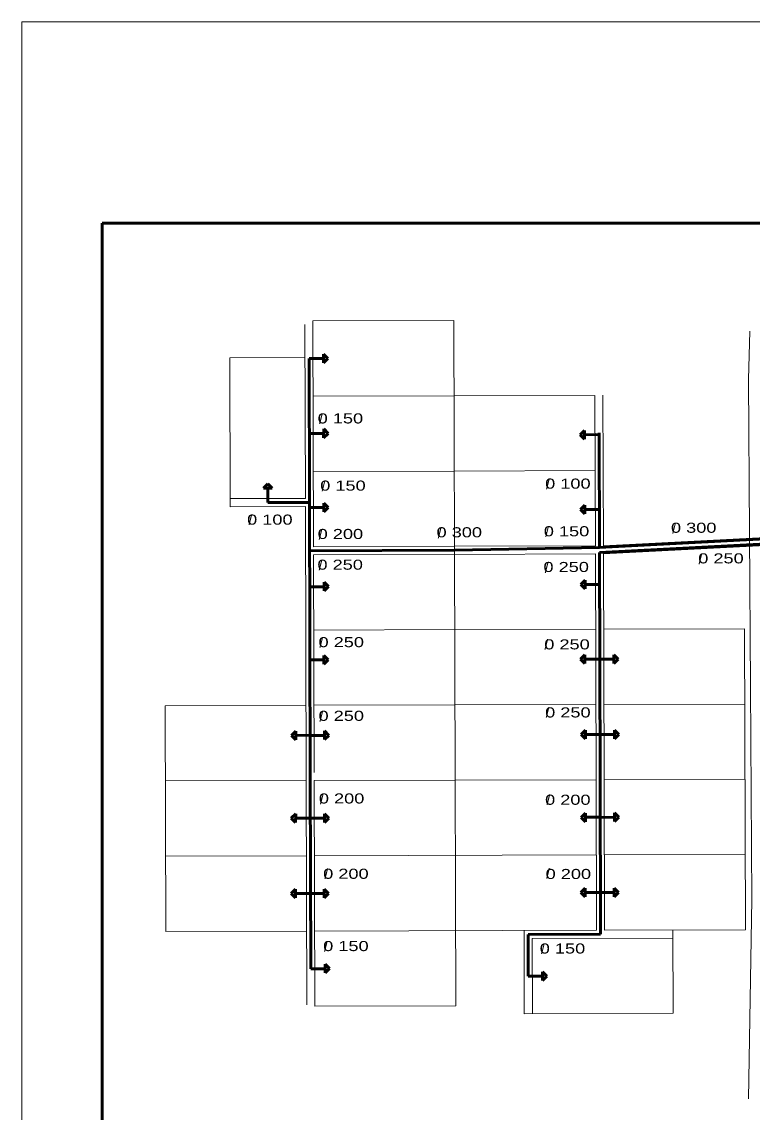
# Model space of a CAD drawing. Extents: x 312964 to 351929, y 9004151 to 9034973.
# Drawn here: x 334316 to 336131, y 9019423 to 9022132 of the extents above; entities that cross this region are included whole.
import ezdxf
from ezdxf.enums import TextEntityAlignment as Align

# ---------------------------------------------------------------- set-up
doc = ezdxf.new("R2010")
doc.units = 0
doc.header["$LTSCALE"] = 10
for name, color, linetype, lineweight in [('1', 7, 'Continuous', 13), ('2', 7, 'Continuous', 53), ('6', 7, 'Continuous', 13)]:
    doc.layers.add(name, color=color, linetype=linetype, lineweight=lineweight)

msp = doc.modelspace()

# ---------------------------------------------------------------- linework, layer by layer
at = {"layer": '1', "lineweight": 53}
for p, q in [((340056.19, 9021632.19), (334516.19, 9021632.19)), ((334516.19, 9021632.19), (334516.19, 9018132.19))]:
    msp.add_line(p, q, dxfattribs=at)
at = {"layer": '1'}
for p, q in [((335019.46, 9021379.9), (335020.74, 9020947.95)), ((335039.43, 9021389.01), (335389.43, 9021390.05)), ((335039.43, 9021389.01), (335041.09, 9020828.01)), ((335389.43, 9021390.05), (335394.47, 9019687.05)), ((334832.7, 9021297.4), (335019.7, 9021297.95)), ((334832.7, 9021297.4), (334833.8, 9020927.4)), ((335039.99, 9021202.01), (335389.98, 9021203.05)), ((335389.98, 9021203.05), (335739.98, 9021204.08)), ((335739.98, 9021204.08), (335741.09, 9020830.08)), ((335759.98, 9021204.14), (335761.09, 9020830.14)), ((335040.54, 9021015.01), (335390.54, 9021016.05)), ((335390.54, 9021016.05), (335740.54, 9021017.08)), ((334833.74, 9020947.4), (335020.74, 9020947.95)), ((334833.8, 9020927.4), (335020.8, 9020927.95)), ((335761.09, 9020830.14), (336163.57, 9020851.16)), ((335041.09, 9020828.01), (335391.09, 9020829.05)), ((335391.09, 9020829.05), (335741.09, 9020830.08)), ((335741.15, 9020810.08), (335742.81, 9020249.09)), ((335761.15, 9020810.14), (336163.49, 9020831.16)), ((335761.15, 9020810.14), (335762.81, 9020249.14)), ((335041.15, 9020808.01), (335042.75, 9020267.01)), ((335041.71, 9020621.01), (335391.7, 9020622.05)), ((335391.7, 9020622.05), (335741.7, 9020623.08)), ((335761.7, 9020623.14), (336111.7, 9020624.18)), ((336111.7, 9020624.18), (336113.91, 9019876.18)), ((334672.26, 9020432.92), (335022.26, 9020433.95)), ((334672.26, 9020432.92), (334673.92, 9019871.92)), ((335762.26, 9020436.14), (336112.25, 9020437.18)), ((334672.81, 9020245.92), (335022.81, 9020246.96)), ((334672.81, 9020245.92), (335022.81, 9020246.96)), ((335042.81, 9020247.01), (335742.81, 9020249.09)), ((335042.81, 9020247.01), (335742.81, 9020249.09)), ((335042.81, 9020247.01), (335044.47, 9019686.02)), ((335742.81, 9020249.09), (335743.92, 9019875.09)), ((335762.81, 9020249.14), (336112.81, 9020250.18)), ((335762.81, 9020249.14), (335763.92, 9019875.15)), ((334673.37, 9020058.92), (335023.37, 9020059.96)), ((335043.37, 9020060.02), (335743.36, 9020062.09)), ((335763.36, 9020062.15), (336113.36, 9020063.18)), ((334673.92, 9019871.92), (335023.92, 9019872.96)), ((335043.92, 9019873.02), (335743.92, 9019875.09)), ((335563.92, 9019874.55), (335564.53, 9019667.56)), ((335763.92, 9019875.15), (336113.91, 9019876.18)), ((335933.91, 9019875.65), (335934.53, 9019668.65)), ((335583.98, 9019854.61), (335933.97, 9019855.65)), ((335583.98, 9019854.61), (335584.53, 9019667.62)), ((335044.47, 9019686.02), (335394.47, 9019687.05)), ((335564.53, 9019667.56), (335934.53, 9019668.65))]:
    msp.add_line(p, q, dxfattribs=at)
msp.add_lwpolyline([(340256.19, 9022132.19), (334316.19, 9022132.19), (334316.19, 9017932.19), (340256.19, 9017932.19)], close=True, dxfattribs=at)
for points in [[(335020.8, 9020927.95), (335022.81, 9020246.96), (335024.46, 9019689.9)], [(335041.15, 9020808.01), (335391.15, 9020809.05), (335741.15, 9020810.08)], [(335042.26, 9020434.01), (335392.26, 9020435.05), (335742.26, 9020436.08)]]:
    msp.add_lwpolyline(points, dxfattribs=at)
at = {"layer": '2'}
for p, q in [((335065.52, 9021284.84), (335065.6, 9021306.4)), ((335076.34, 9021295.58), (335065.6, 9021306.4)), ((335029.71, 9021295.48), (335032.78, 9020256.99)), ((335065.56, 9021295.36), (335029.71, 9021295.48)), ((335076.34, 9021295.58), (335065.52, 9021284.84)), ((335066.11, 9021109.43), (335030.26, 9021109.55)), ((335066.07, 9021098.91), (335066.15, 9021120.47)), ((335076.89, 9021109.65), (335066.07, 9021098.91)), ((335076.89, 9021109.65), (335066.15, 9021120.47)), ((335703.64, 9021106.28), (335714.46, 9021117.02)), ((335714.46, 9021117.02), (335714.39, 9021095.46)), ((335750.26, 9021110.61), (335751.1, 9020825.62)), ((335703.64, 9021106.28), (335714.39, 9021095.46)), ((335714.42, 9021106.5), (335750.27, 9021106.38)), ((334927.17, 9020984.3), (334916.35, 9020973.56)), ((334937.91, 9020973.49), (334916.35, 9020973.56)), ((334927.17, 9020984.3), (334937.91, 9020973.49)), ((334927.39, 9020973.52), (334927.27, 9020937.68)), ((334927.27, 9020937.68), (335030.77, 9020937.98)), ((335066.65, 9020925.39), (335030.8, 9020925.51)), ((335066.62, 9020914.87), (335066.69, 9020936.43)), ((335077.43, 9020925.61), (335066.62, 9020914.87)), ((335077.43, 9020925.61), (335066.69, 9020936.43)), ((335704.19, 9020920.43), (335715.01, 9020931.18)), ((335704.19, 9020920.43), (335714.94, 9020909.62)), ((335715.01, 9020931.18), (335714.94, 9020909.62)), ((335714.97, 9020920.66), (335750.82, 9020920.53)), ((335751.1, 9020825.62), (336163.77, 9020847.17)), ((335031.12, 9020817.98), (335391.12, 9020819.05)), ((335391.12, 9020819.05), (335751.1, 9020825.62)), ((335751.14, 9020813.6), (336164.4, 9020835.18)), ((335751.14, 9020813.6), (335752.78, 9020259.12)), ((335067.24, 9020728.59), (335031.39, 9020728.71)), ((335067.2, 9020718.07), (335067.27, 9020739.63)), ((335078.02, 9020728.81), (335067.2, 9020718.07)), ((335078.02, 9020728.81), (335067.27, 9020739.63)), ((335704.75, 9020734.15), (335715.56, 9020744.89)), ((335704.75, 9020734.15), (335715.49, 9020723.33)), ((335715.56, 9020744.89), (335715.49, 9020723.33)), ((335715.53, 9020734.37), (335751.37, 9020734.25)), ((335066.67, 9020546.56), (335030.82, 9020546.68)), ((335066.63, 9020536.04), (335066.71, 9020557.6)), ((335077.45, 9020546.79), (335066.63, 9020536.04)), ((335077.45, 9020546.79), (335066.71, 9020557.6)), ((335704.19, 9020548.71), (335715, 9020559.46)), ((335704.19, 9020548.71), (335714.93, 9020537.9)), ((335715, 9020559.46), (335714.93, 9020537.9)), ((335714.97, 9020548.94), (335750.82, 9020548.81)), ((335786.66, 9020548.69), (335750.82, 9020548.81)), ((335786.63, 9020538.17), (335786.7, 9020559.73)), ((335797.45, 9020548.92), (335786.63, 9020538.17)), ((335797.45, 9020548.92), (335786.7, 9020559.73)), ((334985.85, 9020359.12), (334996.67, 9020369.87)), ((334985.85, 9020359.12), (334996.59, 9020348.31)), ((334996.67, 9020369.87), (334996.59, 9020348.31)), ((334996.63, 9020359.35), (335032.48, 9020359.23)), ((335068.33, 9020359.11), (335032.48, 9020359.23)), ((335068.29, 9020348.59), (335068.37, 9020370.14)), ((335079.11, 9020359.33), (335068.29, 9020348.59)), ((335079.11, 9020359.33), (335068.37, 9020370.14)), ((335705.85, 9020361.25), (335716.66, 9020372)), ((335705.85, 9020361.25), (335716.59, 9020350.44)), ((335716.66, 9020372), (335716.59, 9020350.44)), ((335716.63, 9020361.48), (335752.48, 9020361.36)), ((335788.33, 9020361.24), (335752.48, 9020361.36)), ((335788.29, 9020350.72), (335788.36, 9020372.27)), ((335799.11, 9020361.46), (335788.29, 9020350.72)), ((335799.11, 9020361.46), (335788.36, 9020372.27)), ((335032.78, 9020256.99), (335034.2, 9019779.49)), ((335752.78, 9020259.12), (335753.95, 9019865.12)), ((334985.76, 9020153.38), (334996.58, 9020164.13)), ((334996.58, 9020164.13), (334996.51, 9020142.57)), ((335068.2, 9020142.84), (335068.28, 9020164.4)), ((335079.02, 9020153.59), (335068.28, 9020164.4)), ((335705.76, 9020155.51), (335716.57, 9020166.26)), ((335716.57, 9020166.26), (335716.5, 9020144.7)), ((335788.2, 9020144.97), (335788.27, 9020166.53)), ((335799.02, 9020155.72), (335788.27, 9020166.53)), ((334985.76, 9020153.38), (334996.51, 9020142.57)), ((334996.54, 9020153.61), (335032.39, 9020153.49)), ((335068.24, 9020153.37), (335032.39, 9020153.49)), ((335079.02, 9020153.59), (335068.2, 9020142.84)), ((335705.76, 9020155.51), (335716.5, 9020144.7)), ((335716.54, 9020155.74), (335752.39, 9020155.62)), ((335788.24, 9020155.5), (335752.39, 9020155.62)), ((335799.02, 9020155.72), (335788.2, 9020144.97)), ((334985.05, 9019966.39), (334995.87, 9019977.13)), ((334995.87, 9019977.13), (334995.8, 9019955.57)), ((335067.49, 9019955.85), (335067.57, 9019977.4)), ((335078.31, 9019966.59), (335067.57, 9019977.4)), ((335705.05, 9019968.52), (335715.87, 9019979.26)), ((335715.87, 9019979.26), (335715.79, 9019957.7)), ((335715.83, 9019968.74), (335751.68, 9019968.62)), ((335787.49, 9019957.98), (335787.56, 9019979.53)), ((335798.31, 9019968.72), (335787.49, 9019957.98)), ((335798.31, 9019968.72), (335787.56, 9019979.53)), ((334985.05, 9019966.39), (334995.8, 9019955.57)), ((334995.83, 9019966.61), (335031.68, 9019966.49)), ((335067.53, 9019966.37), (335031.68, 9019966.49)), ((335078.31, 9019966.59), (335067.49, 9019955.85)), ((335705.05, 9019968.52), (335715.79, 9019957.7)), ((335787.53, 9019968.5), (335751.68, 9019968.62)), ((335573.95, 9019864.58), (335753.95, 9019865.12)), ((335573.95, 9019864.58), (335574.25, 9019761.09)), ((335070.04, 9019779.37), (335034.2, 9019779.49)), ((335070.01, 9019768.85), (335070.08, 9019790.4)), ((335080.82, 9019779.59), (335070.01, 9019768.85)), ((335080.82, 9019779.59), (335070.08, 9019790.4)), ((335610.1, 9019760.96), (335574.25, 9019761.09)), ((335610.06, 9019750.44), (335610.14, 9019772)), ((335620.88, 9019761.19), (335610.06, 9019750.44)), ((335620.88, 9019761.19), (335610.14, 9019772))]:
    msp.add_line(p, q, dxfattribs=at)
at = {"layer": '6'}
for p, q in [((336121.16, 9021243.34), (336124.55, 9021363.92)), ((336126.16, 9020480.99), (336121.16, 9021242.99)), ((336130.16, 9019950.98), (336126.16, 9020480.98)), ((336121.16, 9019456.24), (336130.16, 9019951.24))]:
    msp.add_line(p, q, dxfattribs=at)

# ---------------------------------------------------------------- texts
at = {"layer": '2', "width": 1.35}
for s, p in [('0 150', (335107.66, 9021134.28)), ('0 150', (335114, 9020967.33)), ('0 100', (335672.76, 9020972.25)), ('0 100', (334932.4, 9020882.8)), ('0 200', (335107.66, 9020847.16)), ('0 300', (335402.96, 9020851.36)), ('0 150', (335669.45, 9020853.9)), ('0 300', (335985.35, 9020862.59)), ('0 250', (336053.12, 9020786.54)), ('0 250', (335107.09, 9020770.85)), ('0 250', (335668.54, 9020765.15)), ('0 250', (335109.76, 9020578.4)), ('0 250', (335670.65, 9020572.85)), ('0 250', (335109.76, 9020395.3)), ('0 250', (335672.76, 9020403.78)), ('0 200', (335110.63, 9020189.98)), ('0 200', (335672.63, 9020186.8)), ('0 200', (335121.32, 9020002.88)), ('0 200', (335673.96, 9020002.37)), ('0 150', (335121.32, 9019823.25)), ('0 150', (335659.37, 9019817.2))]:
    msp.add_text(s, height=25, dxfattribs=at).set_placement(p, align=Align.CENTER)
at = {"layer": '2'}
for p in [(335059.35, 9021133.34), (335065.68, 9020965.91), (335623.13, 9020971.2), (334884.09, 9020882.44), (335058.29, 9020845.75), (335354.2, 9020849.36), (335621.14, 9020852.49), (335936.59, 9020860.59), (336001.88, 9020784.42), (335058.29, 9020769.38), (335619.97, 9020763.04), (335060.3, 9020577.66), (335619.13, 9020572.3), (335622.3, 9020403.24), (335060.3, 9020393.81), (335061.42, 9020187.93), (335624.28, 9020186.26), (335072.57, 9020002.34), (335623.41, 9020003.37), (335071.51, 9019821.85), (335610.74, 9019816.34)]:
    msp.add_text('/', height=25, dxfattribs=at).set_placement(p, align=Align.CENTER)

doc.saveas('drawing.dxf')
